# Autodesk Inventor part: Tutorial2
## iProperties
Created: 2009-06
Part Number: Tutorial2
Document SubType Name: Modeling
Designer: Sham
Density: 1 g/cm^3
Author: Sham
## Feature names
1. Extrusion1
2. Extrusion2
3. Extrusion3
4. Extrusion4
5. Extrusion5
6. Mirror1
7. Hole1
